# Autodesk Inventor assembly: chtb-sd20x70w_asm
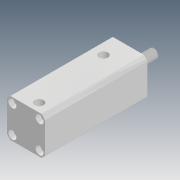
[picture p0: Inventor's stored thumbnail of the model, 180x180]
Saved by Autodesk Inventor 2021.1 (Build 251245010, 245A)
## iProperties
Company: Microsoft
Created: 2018-05
Part Number: chtb-sd20x70w_asm
Description: STEP AP214
Document SubType Name: Assembly
Designer: user
Title: chtb-sd20x70w_asm.STEP
Author: Windows
Revision Number: ÈÎºÎ
Sending System: SolidWorks 2015
Preprocessor: SwSTEP 2.0
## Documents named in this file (4)
- D:\Vault_2016\Projekty\Clamptek\Hydraulic\CHTB\CHTB-20\Inventor\CHTB-SD20x70W\chtb-sd20x70w_asm.iam
- D:\Vault_2016\Projekty\Clamptek\Hydraulic\CHTB\CHTB-20\Inventor\CHTB-SD20x70W\CHTB-SD20X70NBT.ipt
- D:\Vault_2016\Projekty\Clamptek\Hydraulic\CHTB\CHTB-20\Inventor\CHTB-SD20x70W\CHTB-SD20X70WHSG.ipt
- D:\Vault_2016\Projekty\Clamptek\Hydraulic\CHTB\CHTB-20\Inventor\CHTB-SD20x70W\QG.ipt
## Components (3 placed, 3 different names)
1. CHTB-SD20X70NBT_1
2. CHTB-SD20X70WHSG_2
3. QG_3
